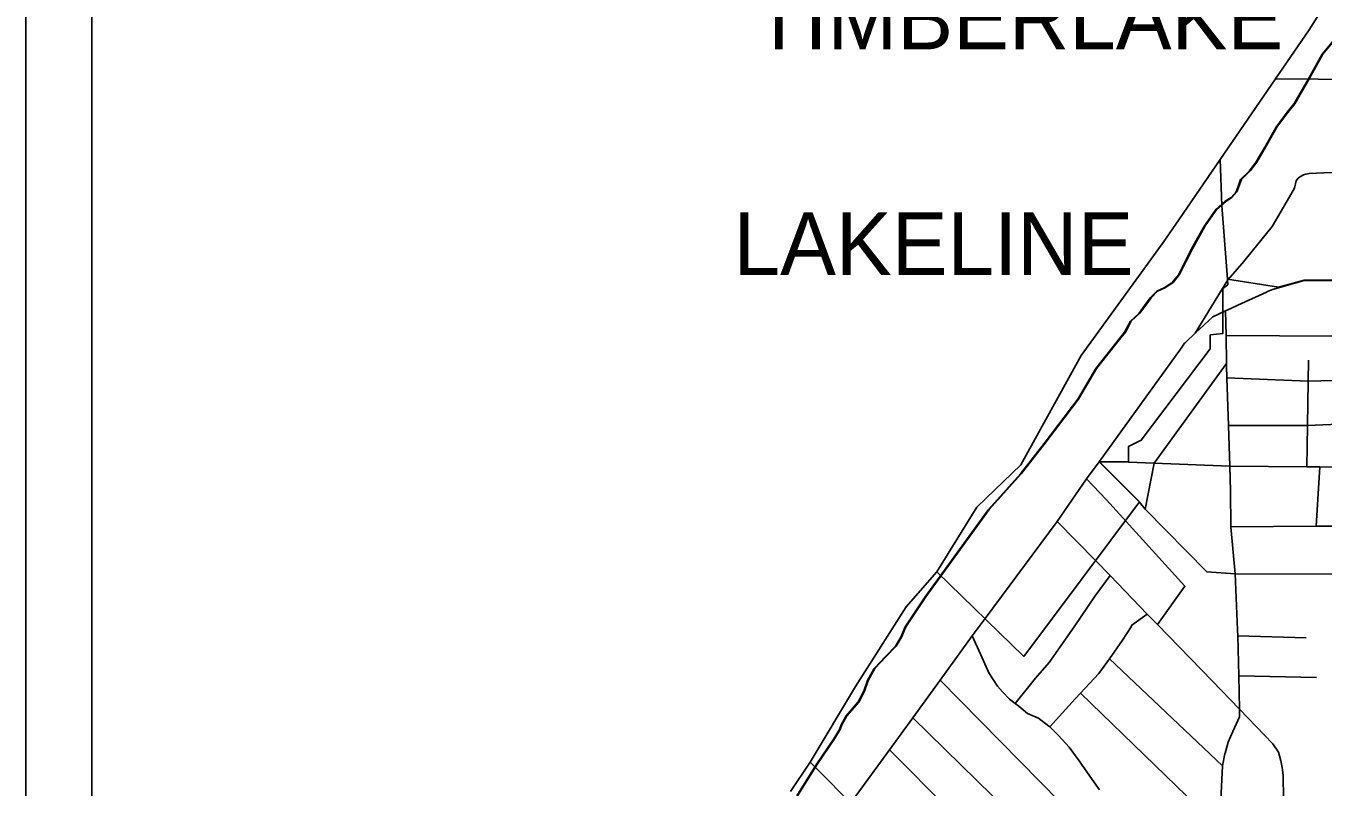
# Model space of a CAD drawing. Extents: x 0 to 34, y 0 to 22.
# Drawn here: x 2 to 3.964, y 15.461 to 16.614 of the extents above; entities that cross this region are included whole.
import ezdxf

# ---------------------------------------------------------------- set-up
doc = ezdxf.new("R2010")
doc.units = 0
for name, color, linetype in [('GM_X_City_Street', 7, 'Continuous'), ('GM_X_Corporation', 7, 'Continuous'), ('GM_X_Corporation_Text', 7, 'Continuous'), ('GM_X_County_Road', 7, 'Continuous'), ('GM_X_Major_Lake', 7, 'Continuous'), ('GM_X_State_Route', 7, 'Continuous'), ('SH_Data', 7, 'Continuous')]:
    doc.layers.add(name, color=color, linetype=linetype)

msp = doc.modelspace()

# ---------------------------------------------------------------- linework, layer by layer
at = {"layer": 'GM_X_City_Street'}
for p, q in [((3.7705, 16.1481), (3.8197, 16.2293)), ((3.8171, 16.1447), (3.9789, 16.1436)), ((3.708, 15.9514), (3.8179, 16.1024)), ((3.6252, 15.9535), (3.6621, 15.9532)), ((3.6252, 15.9535), (3.686, 15.8923)), ((3.6944, 15.8819), (3.708, 15.9514)), ((3.9534, 15.8557), (3.9591, 15.9458)), ((3.6363, 15.8958), (3.6058, 15.9277)), ((3.835, 15.6896), (3.9384, 15.6868)), ((3.6407, 15.6548), (3.8119, 15.4929)), ((3.8362, 15.629), (3.9538, 15.6268)), ((3.5966, 15.6031), (3.8071, 15.3995))]:
    msp.add_line(p, q, dxfattribs=at)
for points in [[(3.8197, 16.2293), (3.8415, 16.2536), (3.8871, 16.3097), (3.9006, 16.3329), (3.9206, 16.368), (3.9231, 16.379), (3.9241, 16.3806), (3.9261, 16.383), (3.93, 16.3855), (3.9345, 16.388), (3.9379, 16.3893), (3.9428, 16.3901), (3.9652, 16.3909), (4.0805, 16.3947), (4.2068, 16.3973), (4.2091, 16.3973), (4.2107, 16.3973), (4.3996, 16.4041), (4.4727, 16.4081)], [(3.9393, 15.9458), (3.9403, 16.0084), (3.9415, 16.0755), (3.942, 16.1074)], [(3.8185, 16.0804), (3.9415, 16.0755), (4.0933, 16.0794)], [(3.8207, 16.0086), (3.9403, 16.0084), (4.0929, 16.0149)], [(3.6621, 15.9532), (3.6694, 15.9531), (3.708, 15.9514), (3.8226, 15.9466), (3.9393, 15.9458), (3.9544, 15.9458), (3.9591, 15.9458), (3.9999, 15.9454), (4.0032, 15.9455), (4.0664, 15.9498), (4.0937, 15.9487), (4.148, 15.9431), (4.2162, 15.9446), (4.3207, 15.9434), (4.3752, 15.9422), (4.4317, 15.9426), (4.4792, 15.9442), (4.4874, 15.9445), (4.5559, 15.9425), (4.7402, 15.9421), (4.9815, 15.9415), (4.9993, 15.9421), (5.011, 15.9519)], [(3.7132, 15.7068), (3.7549, 15.765), (3.6363, 15.8958)], [(3.686, 15.8923), (3.6944, 15.8819), (3.788, 15.7865), (3.8309, 15.7836), (4.1429, 15.7826), (4.2126, 15.7836), (4.3195, 15.7838), (4.3817, 15.7837), (4.4402, 15.7806), (4.4876, 15.7782), (4.4948, 15.7789), (4.5108, 15.7784), (4.7301, 15.7832)], [(3.8243, 15.8547), (3.9534, 15.8557), (4.0009, 15.8561), (4.066, 15.8637)], [(3.6415, 15.7811), (3.6191, 15.7503), (3.587, 15.7035), (3.5492, 15.6494), (3.5287, 15.6257), (3.4978, 15.5875)], [(3.6976, 15.7225), (3.6746, 15.7061), (3.6736, 15.7034), (3.6603, 15.6831), (3.6407, 15.6548), (3.6244, 15.6329), (3.5966, 15.6031), (3.5886, 15.5945), (3.5501, 15.552)], [(3.4329, 15.6899), (3.4458, 15.6608), (3.458, 15.6339), (3.471, 15.6134), (3.4787, 15.6051), (3.4892, 15.5941), (3.4978, 15.5875), (3.5031, 15.5835), (3.5164, 15.5721), (3.5331, 15.565), (3.549, 15.5531), (3.5501, 15.552), (3.5636, 15.5389), (3.5797, 15.5214), (3.5945, 15.5006), (3.6144, 15.4722), (3.6255, 15.4566)], [(3.3842, 15.6228), (3.5956, 15.4075), (3.5975, 15.4056), (3.7686, 15.2319), (3.8048, 15.1952)], [(3.8287, 14.784), (3.8168, 14.9375), (3.8168, 14.9474), (3.8167, 15.0223), (3.8169, 15.0641), (3.8134, 15.0846), (3.8112, 15.0918), (3.8087, 15.099), (3.8042, 15.1062), (3.782, 15.1294), (3.7803, 15.1311), (3.5544, 15.358), (3.536, 15.3761), (3.3428, 15.5658)], [(3.7649, 14.9579), (3.767, 15.0073), (3.7674, 15.0269), (3.7636, 15.0424), (3.7603, 15.0508), (3.7569, 15.0554), (3.7546, 15.0586), (3.7377, 15.0761), (3.6688, 15.1475), (3.4881, 15.3351), (3.3074, 15.5171)]]:
    msp.add_lwpolyline(points, dxfattribs=at)
at = {"layer": 'GM_X_Corporation'}
for points in [[(4.0401, 16.7629), (3.9431, 16.6079), (3.8922, 16.5335), (4.2786, 16.5303)], [(3.9801, 16.5923), (3.9624, 16.5708), (3.9419, 16.5334), (3.9202, 16.496), (3.9094, 16.4828), (3.8929, 16.4605), (3.8793, 16.4359), (3.8627, 16.4076), (3.8526, 16.394), (3.8392, 16.3808), (3.8349, 16.3687), (3.8322, 16.3623), (3.8248, 16.3536), (3.8157, 16.348), (3.8019, 16.336), (3.7845, 16.3111), (3.7655, 16.277), (3.745, 16.2366), (3.7357, 16.2249), (3.7235, 16.217), (3.7124, 16.2118), (3.7024, 16.202), (3.6943, 16.1907), (3.6855, 16.1786), (3.6724, 16.1666), (3.6635, 16.15), (3.6523, 16.1356), (3.62, 16.0949), (3.5929, 16.0484), (3.5416, 15.9813), (3.5058, 15.9353), (3.4574, 15.881), (3.3614, 15.7489), (3.3312, 15.7032), (3.3246, 15.6877), (3.3165, 15.6741), (3.3015, 15.6583), (3.2842, 15.6402), (3.2742, 15.6221), (3.2687, 15.6058), (3.2601, 15.5896), (3.242, 15.5688), (3.2343, 15.5552), (3.2316, 15.548), (3.2231, 15.5337), (3.1964, 15.4944), (3.167, 15.4476)], [(3.9801, 16.5923), (3.9624, 16.5708), (3.9419, 16.5334), (3.9202, 16.496), (3.9094, 16.4828), (3.8929, 16.4605), (3.8793, 16.4359), (3.8627, 16.4076), (3.8526, 16.394), (3.8392, 16.3808), (3.8349, 16.3687), (3.8322, 16.3623), (3.8248, 16.3536), (3.8157, 16.348), (3.8019, 16.336), (3.7845, 16.3111), (3.7655, 16.277), (3.745, 16.2366), (3.7357, 16.2249), (3.7235, 16.217), (3.7124, 16.2118), (3.7024, 16.202), (3.6943, 16.1907), (3.6855, 16.1786), (3.6724, 16.1666), (3.6635, 16.15), (3.6523, 16.1356), (3.62, 16.0949), (3.5929, 16.0484), (3.5416, 15.9813), (3.5058, 15.9353), (3.4574, 15.881), (3.3614, 15.7489), (3.3312, 15.7032), (3.3246, 15.6877), (3.3165, 15.6741), (3.3015, 15.6583), (3.2842, 15.6402), (3.2742, 15.6221), (3.2687, 15.6058), (3.2601, 15.5896), (3.242, 15.5688), (3.2343, 15.5552), (3.2316, 15.548), (3.2231, 15.5337), (3.1964, 15.4944), (3.167, 15.4476)], [(4.085, 16.2301), (3.9352, 16.2287), (3.8967, 16.2178), (3.8193, 16.2299), (3.8194, 16.2292), (3.82, 16.2216), (3.8121, 16.2158), (3.8124, 16.1478), (3.7931, 16.1456), (3.793, 16.1244), (3.6886, 15.9861), (3.6694, 15.9766), (3.6692, 15.9536), (3.625, 15.9541), (3.6858, 15.8929), (3.5109, 15.6585), (3.379, 15.7868), (3.3327, 15.7336), (3.2558, 15.613), (3.1872, 15.4982), (3.7004, 14.9818)], [(3.7004, 14.9818), (3.1872, 15.4982), (3.1574, 15.4538)]]:
    msp.add_lwpolyline(points, dxfattribs=at)
for points in [[(3.8084, 16.4111), (3.8922, 16.5335), (4.2786, 16.5303), (4.4988, 16.5299), (4.5461, 16.5283), (4.5513, 16.4904), (4.5873, 16.4879), (4.5769, 16.4486), (4.5651, 16.4021), (4.5587, 16.3754), (4.5511, 16.3016), (4.5471, 16.2647), (4.5436, 16.2259), (4.3148, 16.2298), (4.085, 16.2301), (3.9352, 16.2287), (3.8967, 16.2178), (3.8193, 16.2299), (3.8106, 16.3415)], [(3.379, 15.7868), (3.4395, 15.8848), (3.5063, 15.9488), (3.5977, 16.1143), (3.7217, 16.2854), (3.7454, 16.3198), (3.8084, 16.4111), (3.8106, 16.3415), (3.8193, 16.2299), (3.8194, 16.2292), (3.82, 16.2216), (3.8121, 16.2158), (3.8124, 16.1478), (3.7931, 16.1456), (3.793, 16.1244), (3.6886, 15.9861), (3.6694, 15.9766), (3.6692, 15.9536), (3.625, 15.9541), (3.6858, 15.8929), (3.5109, 15.6585)]]:
    msp.add_lwpolyline(points, close=True, dxfattribs=at)
at = {"layer": 'GM_X_County_Road'}
msp.add_line((3.5614, 15.8628), (3.6197, 15.8034), dxfattribs=at)
for points in [[(3.8346, 15.699), (3.8309, 15.7836), (3.8243, 15.8547), (3.8237, 15.9094), (3.8226, 15.9466), (3.8207, 16.0086), (3.8185, 16.0804), (3.818, 16.0983), (3.8179, 16.1024), (3.8171, 16.1447), (3.8165, 16.1821)], [(3.6197, 15.8034), (3.6415, 15.7811), (3.6976, 15.7225), (3.7132, 15.7068), (3.7959, 15.6214)], [(3.8156, 15.5122), (3.8204, 15.5285), (3.8274, 15.5449), (3.8372, 15.567), (3.8372, 15.5787), (3.8362, 15.629), (3.835, 15.6896), (3.8346, 15.699)], [(3.7959, 15.6214), (3.8372, 15.5787), (3.8881, 15.5263), (3.8964, 15.5135), (3.9002, 15.5006), (3.9022, 15.4906), (3.9035, 15.4785), (3.9041, 15.4424)], [(3.6901, 15.0236), (3.7377, 15.0761), (3.7655, 15.1068), (3.782, 15.1294), (3.7902, 15.1407), (3.8047, 15.1921), (3.8048, 15.1952), (3.8095, 15.3073), (3.8093, 15.3144), (3.8071, 15.3995), (3.8119, 15.4929), (3.8154, 15.5113), (3.8156, 15.5122)]]:
    msp.add_lwpolyline(points, dxfattribs=at)
at = {"layer": 'GM_X_Major_Lake'}
msp.add_lwpolyline([(3.1681, 15.4475), (3.1975, 15.4944), (3.2241, 15.5336), (3.2326, 15.548), (3.2354, 15.5552), (3.2431, 15.5688), (3.2612, 15.5895), (3.2697, 15.6058), (3.2752, 15.622), (3.2853, 15.6402), (3.3026, 15.6583), (3.3176, 15.6741), (3.3257, 15.6877), (3.3323, 15.7032), (3.3624, 15.7489), (3.4584, 15.881), (3.5069, 15.9352), (3.5427, 15.9812), (3.5939, 16.0484), (3.621, 16.0948), (3.6534, 16.1356), (3.6646, 16.1499), (3.6735, 16.1665), (3.6865, 16.1786), (3.6954, 16.1906), (3.7035, 16.202), (3.7135, 16.2118), (3.7245, 16.217), (3.7368, 16.2248), (3.746, 16.2365), (3.7666, 16.277), (3.7856, 16.311), (3.8029, 16.3359), (3.8167, 16.3479), (3.8259, 16.3536), (3.8332, 16.3622), (3.8359, 16.3687), (3.8403, 16.3808), (3.8537, 16.394), (3.8637, 16.4075), (3.8804, 16.4359), (3.8939, 16.4605), (3.9105, 16.4827), (3.9213, 16.4959), (3.9429, 16.5333), (3.9635, 16.5708), (3.9812, 16.5923)], dxfattribs=at)
at = {"layer": 'GM_X_State_Route'}
for points in [[(3.88, 16.2112), (3.8873, 16.2146), (3.9354, 16.2281), (3.968, 16.2281), (3.9853, 16.2281), (3.9967, 16.2281)], [(3.8349, 16.1905), (3.8782, 16.2104), (3.88, 16.2112)], [(3.7559, 16.1342), (3.7705, 16.1481), (3.797, 16.1732), (3.8165, 16.1821), (3.8241, 16.1856), (3.8349, 16.1905)], [(3.4522, 15.7159), (3.5614, 15.8628), (3.6058, 15.9277), (3.6252, 15.9535), (3.748, 16.124), (3.7544, 16.1329), (3.7559, 16.1342)], [(3.2459, 15.4323), (3.257, 15.4477), (3.3074, 15.5171), (3.3428, 15.5658), (3.3842, 15.6228), (3.4329, 15.6899), (3.4522, 15.7159)]]:
    msp.add_lwpolyline(points, dxfattribs=at)
at = {"layer": 'SH_Data'}
for p, q in [((2, 21), (2, 14)), ((2.1, 20.9), (2.1, 14.1))]:
    msp.add_line(p, q, dxfattribs=at)

# ---------------------------------------------------------------- texts
at = {"layer": 'GM_X_Corporation_Text'}
for s, p in [('TIMBERLAKE', (3.1013, 16.5782)), ('LAKELINE', (3.0715, 16.2365))]:
    msp.add_text(s, height=0.0947, rotation=0, dxfattribs=at).set_placement(p)

doc.saveas('drawing.dxf')
